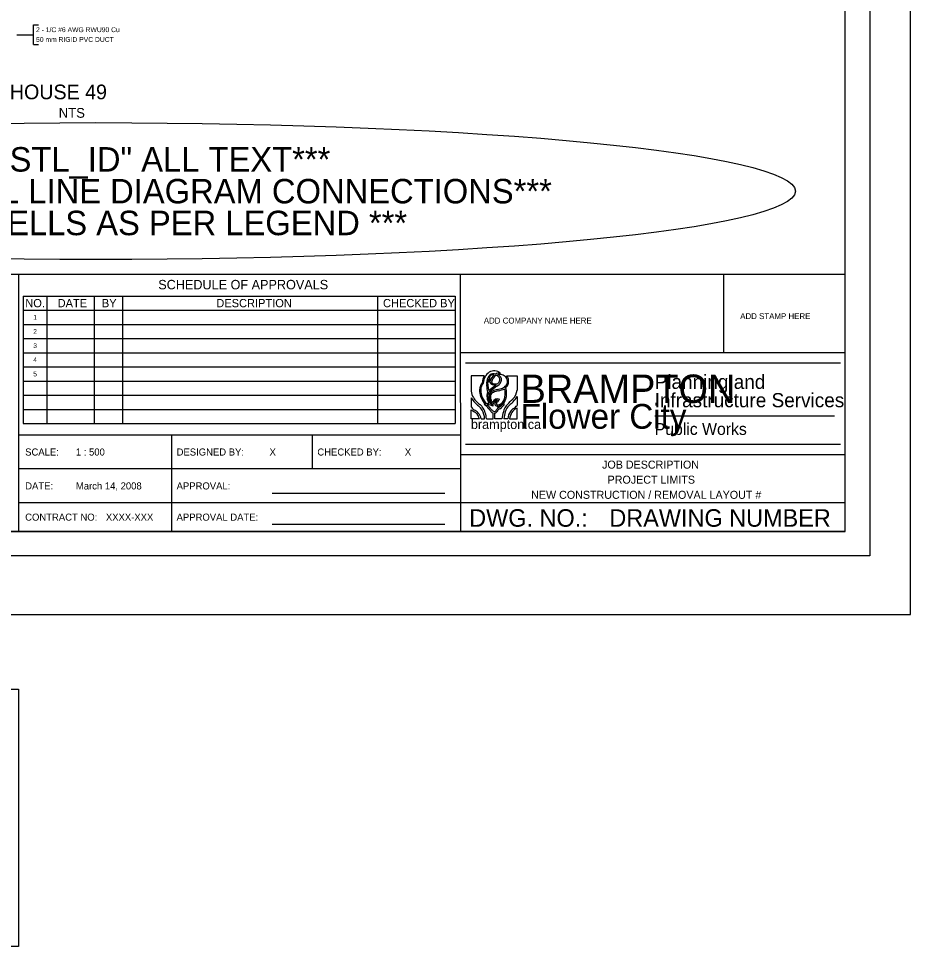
# Model space of a CAD drawing. Extents: x 602909 to 603631, y 4846273 to 4846729.
# Drawn here: x 603194.8 to 603377, y 4846272.8 to 4846462.4 of the extents above; entities that cross this region are included whole.
import ezdxf

# ---------------------------------------------------------------- set-up
doc = ezdxf.new("R2010")
doc.units = 0
for name, color, linetype in [('-PRINT FULLSIZE', 7, 'Continuous'), ('-PRINT HALFSIZE', 7, 'Continuous'), ('ENG_BORDER', 7, 'Continuous'), ('ENG_LOGO', 7, 'Continuous'), ('ENG_TITLEBLOCK', 7, 'Continuous'), ('ENG_TX_LOGO', 7, 'Continuous'), ('ENG_TX_TITLEBLOCK', 7, 'Continuous'), ('ENG_WK_MISC-1', 7, 'Continuous'), ('SL - Border Text', 7, 'Continuous'), ('STL_ID', 7, 'Continuous'), ('STL_WIRING', 7, 'Continuous')]:
    doc.layers.add(name, color=color, linetype=linetype)

# ---------------------------------------------------------------- blocks, each defined once
blk = doc.blocks.new('PIS-PW TITLE-H')
at = {"layer": 'ENG_LOGO'}
for p, q in [((-75.42, 14.45), (-78.15, 14.45)), ((-78.15, 14.45), (-78.15, 11.26)), ((-70.72, 14.45), (-68.47, 14.45)), ((-68.47, 14.45), (-68.47, 11.45)), ((-74.69, 11.23), (-74.85, 12.58)), ((-74.43, 11.34), (-74.65, 13.06)), ((-72.89, 12.5), (-74.43, 11.34)), ((-72.76, 12.26), (-74.31, 11.1)), ((-68.47, 10.08), (-68.47, 8.17)), ((-78.15, 9.79), (-78.15, 7.81)), ((-74.92, 8.64), (-74.39, 8.64)), ((-73.76, 8.31), (-73.76, 8.45)), ((-72.07, 7.93), (-71.51, 8.46)), ((-78.15, 5.39), (-78.15, 7.29)), ((-73.55, 5.39), (-73.55, 6.62)), ((-73.17, 5.39), (-73.17, 6.56)), ((-68.47, 5.39), (-68.47, 7.65)), ((-76.45, 5.39), (-78.15, 5.39)), ((-76.06, 5.39), (-75.33, 5.39)), ((-74.96, 5.39), (-73.55, 5.39)), ((-71.67, 5.39), (-73.17, 5.39)), ((-70.41, 5.39), (-71.29, 5.39)), ((-70.05, 5.39), (-68.47, 5.39))]:
    blk.add_line(p, q, dxfattribs=at)
for centre, major_axis, start_param, end_param in [((-73.93, 13.08), (0, 2.24), 0.915828, 1.568717), ((-73.32, 12.77), (0, 2.75), 5.678233, 7.807497), ((-73.37, 13.09), (0, -1.84), 3.318986, 4.976585), ((-73.42, 13.22), (0, 1.47), 1.119551, 1.674398), ((-73.07, 13.94), (0, -1.75), 4.758696, 4.974719), ((-73.69, 13.89), (0, 0.753), 1.423327, 2.376918), ((-73.81, 14), (0, 0.606), 0.666047, 1.576027), ((-72, 12.52), (0, 2.67), 0.628774, 1.255965), ((-73.5, 13.33), (0, 1.36), 6.118882, 6.855525), ((-71.91, 12.4), (0, 2.47), 0.484278, 1.276713), ((-73.45, 13.49), (0, 1.43), 5.937042, 6.443816), ((-72.17, 12.32), (0, 2.72), 6.209925, 6.677582), ((-73.16, 13.3), (0, 1.33), 5.514665, 6.02559), ((-72.16, 12.72), (0, 2.07), 6.104016, 6.552384), ((-72.88, 13.34), (0, 1.4), 5.100192, 6.058655), ((-72.72, 13.61), (0, 0.767), 4.934552, 5.720905), ((-72.91, 13.71), (0, -0.969), 0.785512, 1.640949), ((-72.69, 13.68), (0, 1.09), 4.195874, 4.894963), ((-72.33, 11.8), (0, 3), 5.705811, 6.088794), ((-71.57, 13.27), (0, 1.28), 4.747453, 5.681752), ((-71.24, 13.43), (0, 1.19), 4.858966, 5.733736), ((-74.49, 11.45), (0, 2.27), 0.764321, 1.571722), ((-74.55, 11.5), (0, 1.9), 0.74139, 1.563754), ((-75.01, 12.56), (0, -0.186), 1.717889, 1.834992), ((-73.96, 13.66), (0, -0.65), 4.989814, 5.515803), ((-73, 14.66), (0, -2.16), 5.455385, 6.346676), ((-73.1, 14.2), (0, -1.44), 5.558935, 6.198642), ((-73, 14.01), (0, -1.26), 6.098575, 6.969537), ((-73.81, 14.79), (0, -2.82), 0.460861, 0.945922), ((-74.45, 24.58), (0, -13.19), 0.161819, 0.267812), ((-72.14, 13.9), (0, -2.16), 0.344201, 0.831804), ((-72.01, 13.79), (0, -2.29), 0.654188, 1.084874), ((-74.63, 10.73), (0, -4.7), 1.565289, 1.83996), ((-71.33, 13.22), (0, 0.997), 3.823835, 4.807307), ((-72.43, 13.38), (0, -2.61), 1.316711, 1.656268), ((-76.01, 11.44), (0, -2.56), 4.785712, 5.370532), ((-73.65, 13.61), (0, -6.12), 5.369755, 5.566262), ((-74.17, 11.24), (0, 2.66), 1.493845, 2.002346), ((-73.58, 11.27), (0, -3.33), 5.06368, 5.674398), ((-73.24, 11.46), (0, 3.46), 1.555738, 2.522651), ((-72.88, 10.15), (0, 2.35), 1.184297, 2.265825), ((-74.99, 11.18), (0, 0.371), 4.32589, 4.859481), ((-72.5, 10.29), (0, -2.55), 4.68622, 4.981796), ((-73.83, 10.33), (0, 0.964), 0.63706, 1.540523), ((-72.74, 10.03), (0, 1.93), 1.258524, 1.853874), ((-73.29, 9.91), (0, 1.38), 0.28455, 1.028854), ((-73.1, 9.94), (0, 1.21), 1.326911, 2.090694), ((-73.34, 10.1), (0, 0.888), 0.179588, 1.425103), ((-71.39, 4.29), (0, 7.44), 0.207106, 0.364997), ((-71.81, 5.89), (0, 5.46), 0.147367, 0.372097), ((-74.01, 21.47), (0, -10.34), 0.177455, 0.344982), ((-72.98, 10.56), (0, -2.73), 0.78097, 1.623824), ((-73.76, 10.77), (0, 3.34), 4.273394, 5.005808), ((-71.01, 11.91), (0, -3.07), 0.712478, 1.421371), ((-71.69, 12.5), (0, -4.55), 0.682687, 1.010528), ((-75.36, 11.97), (0, -3.98), 5.292666, 5.605077), ((-74.17, 13.11), (0, -5.77), 5.537119, 5.75381), ((-11.92, 112.2), (0, -129.21), 5.63745, 5.644913), ((-78.53, 4.94), (0, 3.93), 5.320654, 5.659535), ((-77.29, 6.41), (0, 2.29), 5.416876, 5.78378), ((-77.88, 5.61), (0, 3.35), 5.018027, 5.462353), ((-74.77, 7.29), (0, 1.34), 0.365522, 0.597805), ((-77.01, 4.73), (0, 4.14), 5.439641, 5.800947), ((-74.75, 5.22), (0, 3.14), 5.823202, 6.334077), ((-77.76, 3.17), (0, 6.23), 5.482733, 5.697338), ((-72.53, 10.38), (0, -2.54), 5.019488, 5.665896), ((-72.42, 10.14), (0, -2.33), 4.995413, 5.526463), ((-72.63, 10.06), (0, -1.76), 5.131028, 5.477302), ((-72.62, 8.16), (0, 1.44), 5.87892, 7.368381), ((-72.6, 8.21), (0, -1.19), 3.173377, 4.865507), ((-72.84, 8.49), (0, 0.39), 1.287529, 2.899642), ((-72.16, 8.3), (0, 1.23), 0.477744, 1.324571), ((-72.57, 9.14), (0, -1.11), 5.896411, 6.466099), ((-72.62, 8.59), (0, 0.276), 0.693494, 2.795441), ((-71.13, 7.42), (0, 2.4), 0.532188, 0.957727), ((-72.57, 10.32), (0, -2), 6.206413, 6.519617), ((-73.45, 12.88), (0, -4.98), 0.25264, 0.48256), ((-73.31, 10.42), (0, -2.89), 0.390063, 0.537232), ((-72.98, 10.64), (0, -2.45), 0.401305, 1.020747), ((-74.54, 11.95), (0, -5.35), 0.664019, 0.865631), ((-71.66, 7.54), (0, 1.13), 5.695616, 5.978543), ((-69.07, 6.19), (0, 2.82), 0.6523, 1.336939), ((-68.18, 5.39), (0, 3.66), 0.690534, 1.157714), ((-96.81, 48.11), (0, -50.61), 0.669806, 0.705808), ((-82.82, 29.47), (0, -26.1), 0.619451, 0.667551), ((-75.9, 20.01), (0, -14.8), 0.573803, 0.643743), ((-73.45, 15.04), (0, -9.15), 5.623762, 5.757196), ((-74.61, 13.52), (0, -7.52), 5.687848, 5.809574), ((-78.43, 4.59), (0, 2.5), 5.497917, 5.817483), ((-79.56, 2.67), (0, 5.21), 5.540505, 5.738863), ((-78.51, 4.55), (0, 2.6), 5.039091, 5.480629), ((-78.45, 4.47), (0, 3), 5.021624, 5.458474), ((-78.36, 5.18), (0, 3.62), 4.76812, 5.296774), ((-78.91, 4.92), (0, 4.75), 4.811691, 5.079969), ((-85.55, -5.35), (0, 18.48), 5.441321, 5.480214), ((-72.71, 8.74), (0, -2), 5.382989, 5.704264), ((-73.35, 7.64), (0, -1.05), 5.423199, 6.055208), ((-73.3, 7.54), (0, -0.612), 5.581796, 6.941571), ((-73.56, 7.96), (0, -1.47), 0.32402, 1.048968), ((-75.34, 9.63), (0, -3.81), 0.828888, 0.938456), ((-72.28, 7.12), (0, 0.637), 0.214109, 1.153309), ((-71.86, 6.52), (0, 1.03), 0.422403, 0.821661), ((-73.45, 10.87), (0, -3.72), 0.408149, 0.566756), ((-65.77, 4.42), (0, 7.11), 1.223572, 1.434629), ((-61.41, 3.3), (0, 11.98), 1.268607, 1.395258), ((-68.35, 5.26), (0, 2.47), 0.824174, 1.519908), ((-67.53, 4.86), (0, 3.06), 0.923116, 1.39853), ((-68.28, 5.34), (0, 2.48), 0.445246, 0.869293), ((-67.08, 3.92), (0, 4.08), 0.417687, 0.818457)]:
    blk.add_ellipse(centre, major_axis=major_axis, ratio=0.837209, start_param=start_param, end_param=end_param, dxfattribs=at)
at = {"layer": 'ENG_TITLEBLOCK'}
for p, q in [((-79.4, 17.2), (0, 17.2)), ((-39.34, 6.03), (-1.27, 6.04)), ((-79.4, 0), (0, 0))]:
    blk.add_line(p, q, dxfattribs=at)
at = {"layer": 'ENG_TX_LOGO'}
blk.add_text('brampton.ca', height=2, rotation=0.002, dxfattribs=at).set_placement((-78.24, 3.21))
at = {"layer": 'ENG_TX_TITLEBLOCK'}
for s, height, p in [('BRAMPTON', 6, (-67.72, 8.74)), ('Planning and', 3, (-39.34, 11.71)), ('Infrastructure Services', 3, (-39.34, 7.82)), ('Flower City', 5.25, (-67.72, 3.27)), ('Public Works', 2.5, (-39.34, 1.97))]:
    blk.add_text(s, height=height, rotation=0.0021, dxfattribs=at).set_placement(p)

msp = doc.modelspace()

# ---------------------------------------------------------------- linework, layer by layer
at = {"layer": '-PRINT FULLSIZE'}
msp.add_lwpolyline([(602930, 4846340.65), (603377.03, 4846340.65), (603377.03, 4846645.65), (602930, 4846645.65)], close=True, dxfattribs=at)
at = {"layer": '-PRINT HALFSIZE'}
msp.add_lwpolyline([(602959.8, 4846631.64), (603368.72, 4846631.64), (603368.72, 4846352.64), (602959.8, 4846352.64)], close=True, dxfattribs=at)
at = {"layer": 'ENG_BORDER'}
for p, q in [((603363.72, 4846357.64), (603363.72, 4846626.85)), ((602977.52, 4846410.23), (603363.74, 4846410.23)), ((603194.76, 4846410.25), (603194.76, 4846357.64)), ((603285.12, 4846357.64), (603285.08, 4846410.25)), ((603338.86, 4846394.19), (603338.86, 4846410.23)), ((603285.09, 4846394.19), (603363.72, 4846394.19)), ((603285.11, 4846377.32), (603194.76, 4846377.32)), ((603226.09, 4846357.72), (603226.09, 4846377.32)), ((603254.8, 4846370.39), (603254.8, 4846377.32)), ((603285.23, 4846373.35), (603363.75, 4846373.35)), ((603285.14, 4846370.39), (603194.76, 4846370.39)), ((603363.66, 4846363.45), (603194.76, 4846363.45)), ((603363.72, 4846357.64), (602977.52, 4846357.64))]:
    msp.add_line(p, q, dxfattribs=at)
for points in [[(602977.52, 4846357.64), (603363.72, 4846357.64), (603363.72, 4846626.64), (602977.52, 4846626.64)], [(603054.8, 4846325.39), (603194.76, 4846325.39), (603194.76, 4846272.8), (603054.8, 4846272.8)]]:
    msp.add_lwpolyline(points, close=True, dxfattribs=at)
at = {"layer": 'ENG_TX_TITLEBLOCK'}
for points in [[(603246.57, 4846365.47), (603281.85, 4846365.47)], [(603246.57, 4846359.1), (603281.85, 4846359.1)]]:
    msp.add_lwpolyline(points, dxfattribs=at)
at = {"layer": 'SL - Border Text'}
for p, q in [((603195.73, 4846405.73), (603195.73, 4846379.66)), ((603195.73, 4846405.73), (603284.02, 4846405.73)), ((603200.56, 4846405.73), (603200.56, 4846379.66)), ((603210.21, 4846405.73), (603210.21, 4846379.66)), ((603216, 4846405.73), (603216, 4846379.66)), ((603268.14, 4846405.73), (603268.14, 4846379.66)), ((603284.02, 4846405.73), (603284.02, 4846379.66)), ((603195.73, 4846402.84), (603284.02, 4846402.84)), ((603195.73, 4846399.94), (603284.02, 4846399.94)), ((603195.73, 4846397.04), (603284.02, 4846397.04)), ((603195.73, 4846394.15), (603284.02, 4846394.15)), ((603195.73, 4846391.25), (603284.02, 4846391.25)), ((603195.73, 4846388.35), (603284.02, 4846388.35)), ((603195.73, 4846385.46), (603284.02, 4846385.46)), ((603195.73, 4846382.56), (603284.02, 4846382.56)), ((603195.73, 4846379.66), (603284.02, 4846379.66))]:
    msp.add_line(p, q, dxfattribs=at)
at = {"layer": 'STL_ID'}
msp.add_ellipse((603210.54, 4846427.17), major_axis=(142.98, 0), ratio=0.097916, dxfattribs=at)
at = {"layer": 'STL_WIRING'}
for p, q in [((603197.83, 4846461.17), (603198.83, 4846461.17)), ((603194.43, 4846459.15), (603197.81, 4846459.15)), ((603197.81, 4846457.13), (603198.81, 4846457.13))]:
    msp.add_line(p, q, dxfattribs=at)
msp.add_lwpolyline([(603197.81, 4846457.13), (603197.81, 4846461.17)], dxfattribs=at)

# ---------------------------------------------------------------- block references
at = {"layer": 'ENG_WK_MISC-1', "xscale": 0.9654884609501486, "yscale": 0.9654884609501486}
msp.add_blockref('PIS-PW TITLE-H', (603362.74, 4846375.45), dxfattribs=at)

# ---------------------------------------------------------------- texts
at = {"layer": 'ENG_TX_TITLEBLOCK'}
for s, height, p in [('STREET D - HOUSE 21 TO HOUSE 49', 3, (603141.94, 4846445.95)), ('NTS', 2, (603202.97, 4846442.17)), ('***USE LAYER "STL_ID" ALL TEXT***', 5, (603143.36, 4846431.17)), ('***USE LAYER "STL_WIRING" FOR ALL LINE DIAGRAM CONNECTIONS***', 5, (603072.36, 4846424.67)), ('***USE APPROPRIATE CELLS AS PER LEGEND ***', 5, (603114.76, 4846418.17)), ('SCALE:', 1.448, (603196.11, 4846373.13)), ('DATE:', 1.448, (603196.11, 4846366.2))]:
    msp.add_text(s, height=height, dxfattribs=at).set_placement(p)
for s, height, rotation, p in [('SCHEDULE OF APPROVALS', 1.931, 360, (603223.31, 4846407.1)), ('NO.', 1.69, 360, (603196.13, 4846403.44)), ('DATE', 1.69, 360, (603202.74, 4846403.44)), ('BY', 1.69, 360, (603211.78, 4846403.44)), ('DESCRIPTION', 1.6896, 360, (603235.17, 4846403.44)), ('CHECKED BY', 1.69, 360, (603269.24, 4846403.44)), ('1', 0.965, 359.9999, (603197.77, 4846400.9)), ('ADD STAMP HERE', 1.2069, 360, (603342.24, 4846401.02)), ('ADD COMPANY NAME HERE', 1.2069, 360, (603289.84, 4846400.11)), ('2', 0.965, 359.9999, (603197.77, 4846398.01)), ('3', 0.965, 359.9999, (603197.77, 4846395.11)), ('4', 0.965, 359.9999, (603197.77, 4846392.22)), ('5', 0.965, 359.9999, (603197.77, 4846389.32)), ('1 : 500', 1.448, 360, (603206.47, 4846373.13)), ('DESIGNED BY:', 1.4482, 360, (603227.06, 4846373.13)), ('X', 1.45, 360, (603246.05, 4846373.13)), ('CHECKED BY:', 1.4482, 360, (603255.82, 4846373.13)), ('X', 1.45, 360, (603273.7, 4846373.13)), ('JOB DESCRIPTION', 1.6356, 360, (603314.01, 4846370.46)), ('March 14, 2008', 1.4482, 360, (603206.47, 4846366.2)), ('APPROVAL:', 1.448, 360, (603227.06, 4846366.2)), ('PROJECT LIMITS', 1.6356, 360, (603315.14, 4846367.38)), ('NEW CONSTRUCTION / REMOVAL LAYOUT #', 1.6356, 360, (603299.52, 4846364.29)), ('DWG. NO.:', 3.583, 360, (603286.86, 4846358.58)), ('DRAWING NUMBER', 3.583, 360, (603315.5, 4846358.58)), ('CONTRACT NO:', 1.4482, 360, (603196.11, 4846359.82)), ('XXXX-XXX', 1.448, 360, (603212.61, 4846359.82)), ('APPROVAL DATE:', 1.4482, 360, (603227.06, 4846359.82))]:
    msp.add_text(s, height=height, rotation=rotation, dxfattribs=at).set_placement(p)
at = {"layer": 'STL_ID'}
for s, p in [('2 - 1/C #6 AWG RWU90 Cu', (603198.33, 4846459.67)), ('50 mm RIGID PVC DUCT', (603198.33, 4846457.67))]:
    msp.add_text(s, height=1, dxfattribs=at).set_placement(p)

doc.saveas('drawing.dxf')
